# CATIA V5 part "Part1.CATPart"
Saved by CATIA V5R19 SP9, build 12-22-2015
Part number: Part1
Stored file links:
  Z:\charly_robot\plaque a trous\Part1.CATPart
  Z:\charly_robot\plaque a trous\Product1.CATProduct
  Z:\charly_robot\plaque a trous\Part2.CATPart
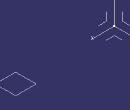
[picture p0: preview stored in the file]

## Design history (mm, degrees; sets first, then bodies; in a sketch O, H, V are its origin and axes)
AxisSystem1: origin (0, 0, 0), X (1, 0, 0), Y (0, 1, 0), Z (0, 0, 1)
Set1
  DatumSurface1: linked copy from another document
Body1 (main body)
  Plane1: type Offset, RefPlane DatumSurface1, Offset 5, reversed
